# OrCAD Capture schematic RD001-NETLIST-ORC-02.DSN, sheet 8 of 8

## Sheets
8 1: size A3
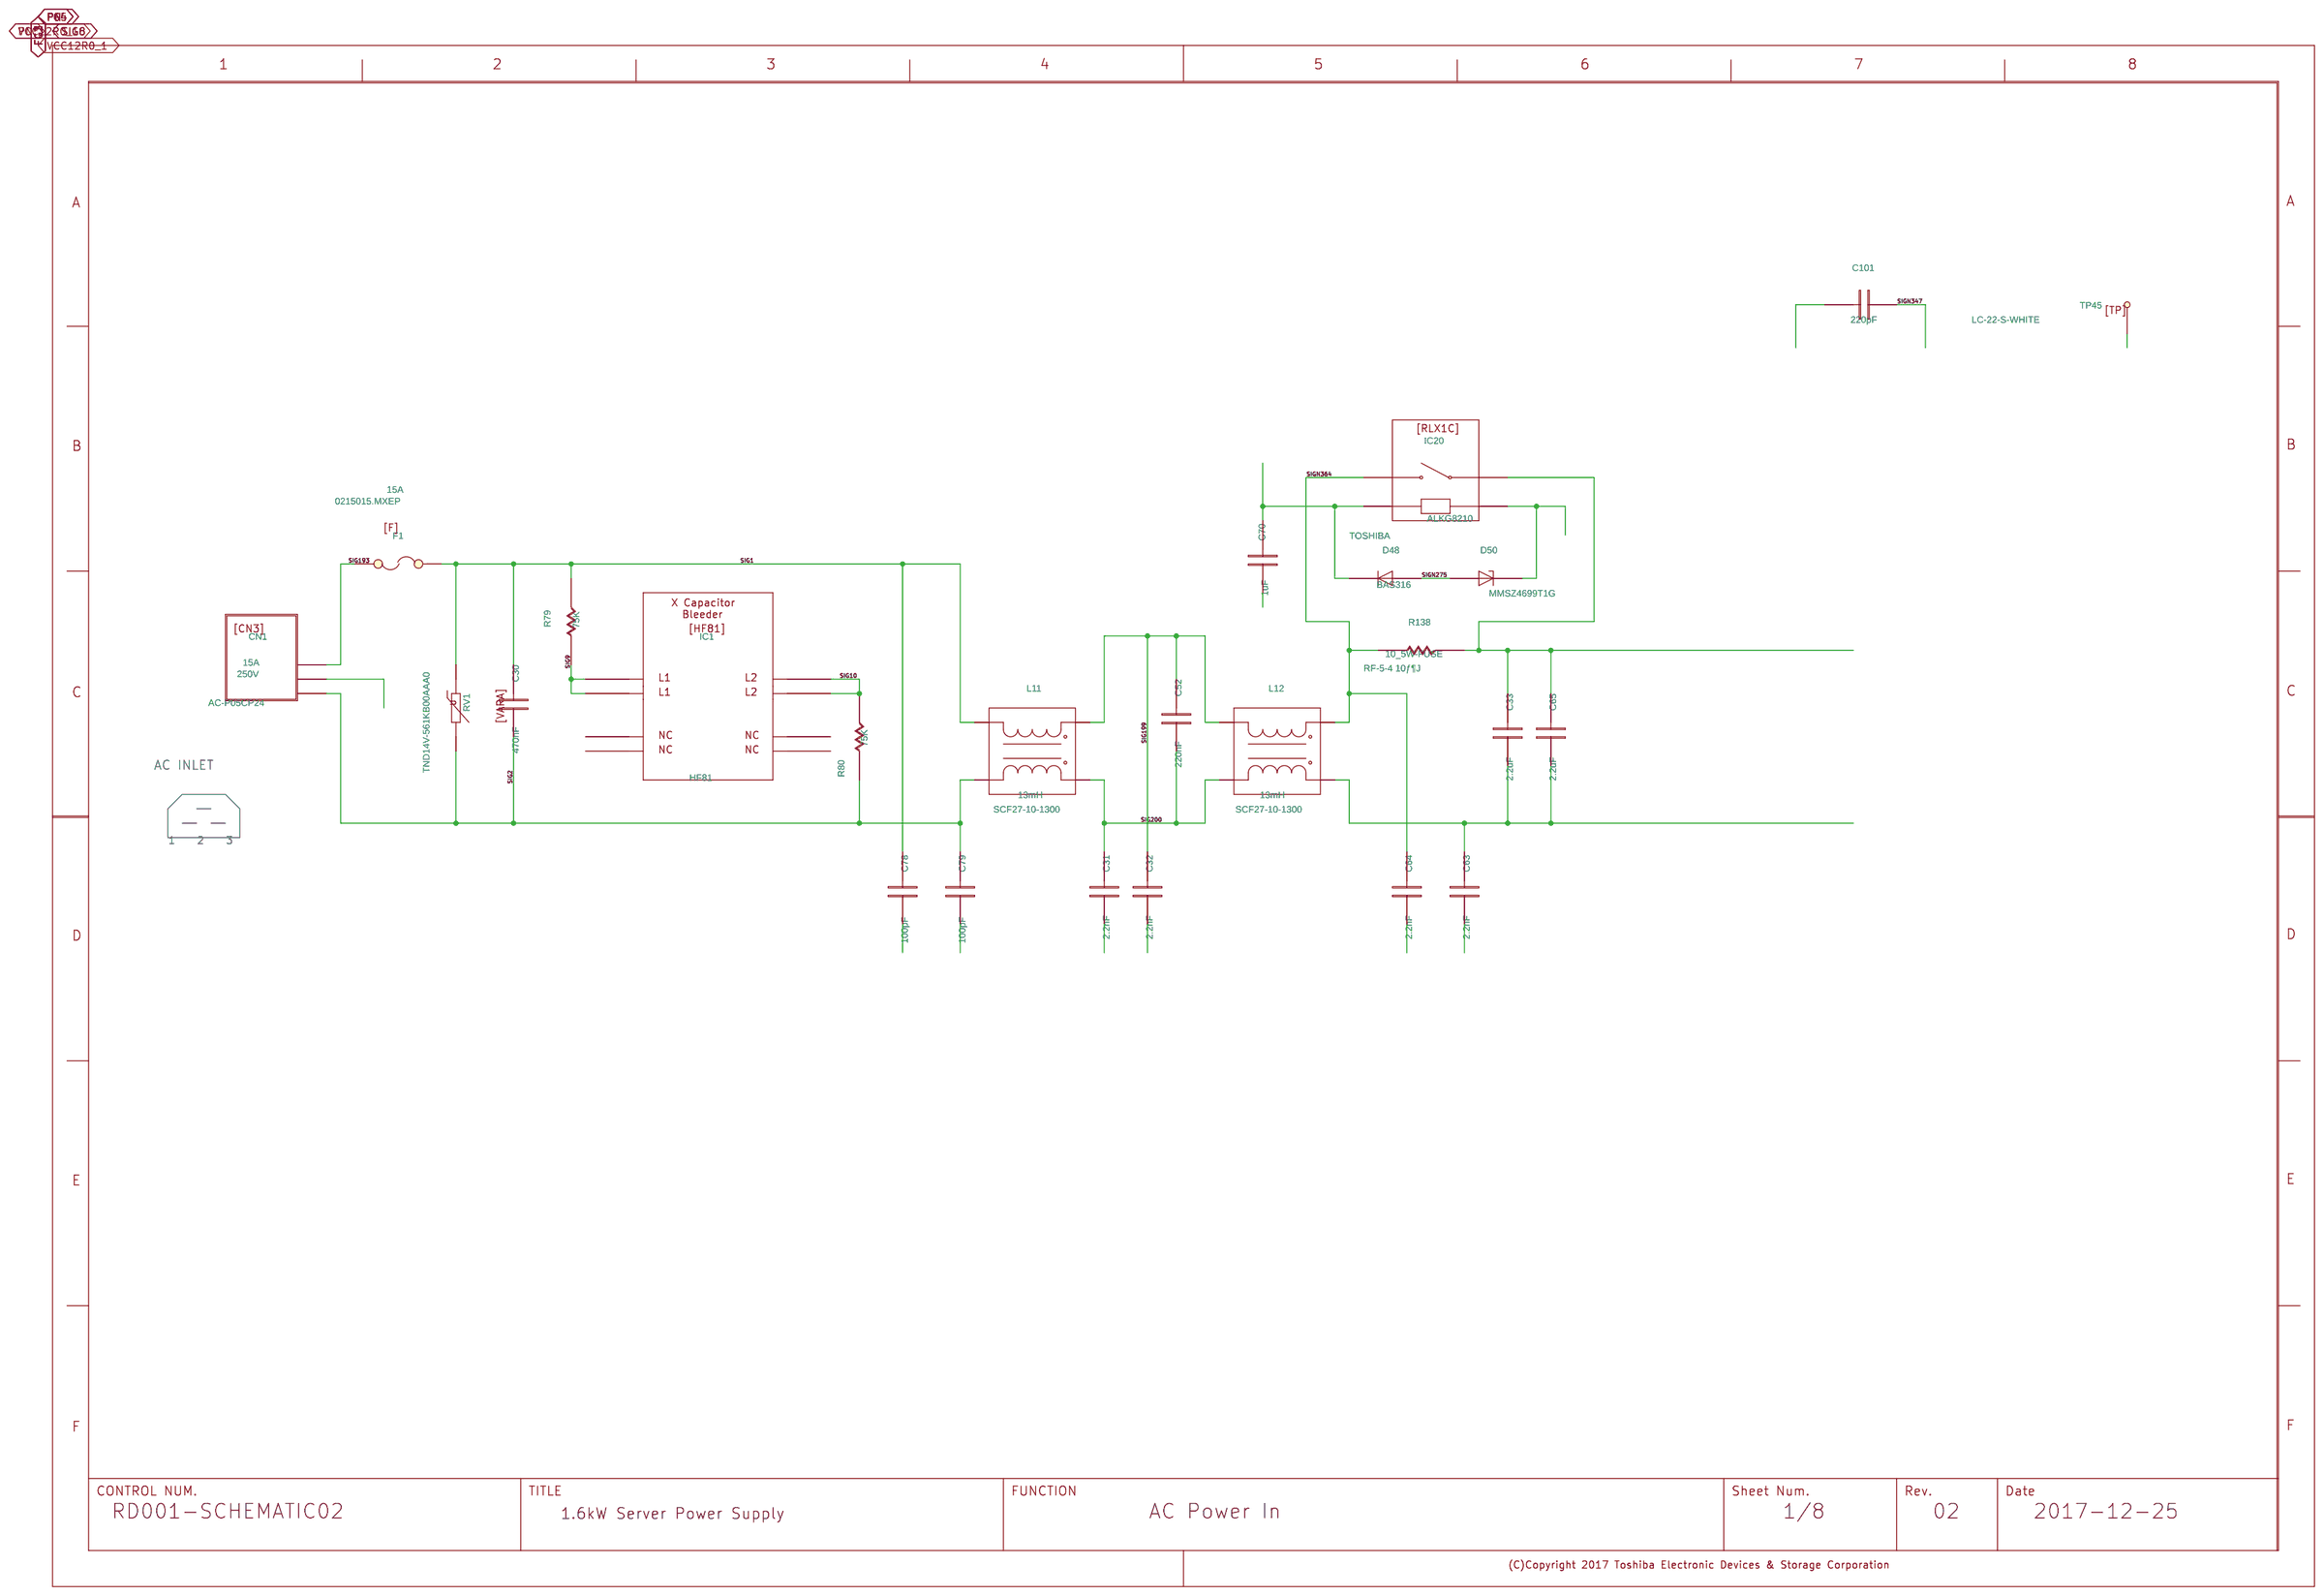
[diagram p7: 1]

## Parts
C30  C
C31  C
C32  C
C33  C
C52  C
C63  C
C64  C
C65  C
C70  C
C78  C
C79  C
C101  C
CN1  CN3
D48  D
D50  ZD
F1  F
IC1  L81
IC20  RLX1C
L11  HM-DLWHN6702
L12  HM-DLWHN6702
R79  R
R80  R
R138  R
RV1  VARA
TP45  TP
U?#7  WAKU_DEF100

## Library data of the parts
C30 = C: ADSMODELNAME: s_GRM32MR72A474KA01L; CAPACITANCETOLE: K; COMP: PRT_19; COMPONENTTYPE: 4; GCOUNT: 1; MAKER: OKAYA; MAXGCOUNT: 1; NOMINALCAPACITA: 470n; RATEDVOLTAGE: 100; SIZECODESMD: 3225; VAL1: 470nF; VAL2: 275V,}10%; VAL3: LE474-M
C31 = C: ADSMODELNAME: s_ECKNTS222ME; CAPACITANCETOLE: M; CDMASTERCADCELG: DC0284; CHIPSIZE: [hsb`7.5mmió]; COMP: PRT_13; COMPONENTTYPE: 4; FNLEADFREETHET1GT2GMCTH1: N_N_N; GCOUNT: 1; MAKER: MURATA; MAXGCOUNT: 1; NOMINALCAPACITA: 2.2n; OUMECLASSIFICATION: ƒZƒ‰ƒ~ƒbƒNƒRƒ“ƒfƒ“ƒT; OUMEMAKER: NAE pi\jbNGNgjbNfoCX; OUMEMAKERKATAMEI: ECKNTS222ME; PMPRODUCTSTYPEG: ES; QUADMODEL: CON_2.2N; RATEDVOLTAGE: 250; SIZECODESMD: DIP; TEMPCHARACTERI2: E; VAL1: 2.2nF; VAL2: 250V,}20%; VAL3: DE2E3KY222MN3AM02F
C32 = C: ADSCNVFLAG: ON; ADSMODELNAME: s_ECKNTS222ME; CAPACITANCETOLE: M; CDMASTERCADCELG: DC0284; CHIPSIZE: [hsb`7.5mmió]; COMP: PRT_13; COMPONENTTYPE: 4; FNLEADFREETHET1GT2GMCTH1: N_N_N; GCOUNT: 1; ICX_PART_MODEL: CON_2.2N; MAKER: MURATA; MAXGCOUNT: 1; NOMINALCAPACITA: 2.2n; OUMECLASSIFICATION: ƒZƒ‰ƒ~ƒbƒNƒRƒ“ƒfƒ“ƒT; OUMEMAKER: NAE pi\jbNGNgjbNfoCX; OUMEMAKERKATAMEI: ECKNTS222ME; PMPRODUCTSTYPEG: ES; QUADMODEL: CON_2.2N; RATEDVOLTAGE: 250; SIZECODESMD: DIP; SQ_PART_MODEL: CON_2.2N; TEMPCHARACTERI2: E; VAL1: 2.2nF; VAL2: 250V,}20%; VAL3: DE2E3KY222MN3AM02F
C33 = C: CAPACITANCETOLE: K; CDMASTERCADCELG: DC0511; COMP: PRT_18; COMPONENTTYPE: 4; FNLEADFREETHET1GT2GMCTH1: 9_N_N; GCOUNT: 1; MAKER: Wurth; MAXGCOUNT: 1; NOMINALCAPACITA: 2.2u; OUMECLASSIFICATION: ƒtƒBƒ‹ƒƒRƒ“ƒfƒ“ƒT; OUMEMAKER: CHM “ú–{ƒPƒ~ƒRƒ“; OUMEMAKERKATAMEI: TACB2E225K; QUADMODEL: CON_2.2U; RATEDVOLTAGE: 250; SIZECODESMD: DIP; VAL1: 2.2uF; VAL2: 275V,}10%; VAL3: 890324026034CS
C52 = C: CAPACITANCETOLE: M; COMP: PRT_17; COMPONENTTYPE: 4; FNLEADFREETHET1GT2GMCTH1: N_N_N; GCOUNT: 1; MAKER: OKAYA; MAXGCOUNT: 1; NOMINALCAPACITA: 220n; OUMECLASSIFICATION: ƒtƒBƒ‹ƒƒRƒ“ƒfƒ“ƒT; OUMEMAKER: NIS ƒjƒbƒZƒC“d‹@; OUMEMAKERKATAMEI: R40KI322000**M; QUADMODEL: CON_220N; RATEDVOLTAGE: 275; SIZECODESMD: DIP; VAL1: 220nF; VAL2: 275V,}10%; VAL3: LE224-M
C63 C64 = C: ADSMODELNAME: s_DE2E3KY222MN3AM02F; CAPACITANCETOLE: M; CDMASTERCADCELG: SIK0018; CHIPSIZE: [hsb`7.5mmió]; COMP: PRT_13; COMPONENTTYPE: 4; FNLEADFREETHET1GT2GMCTH1: N_N_N; GCOUNT: 1; MAKER: MURATA; MAXGCOUNT: 1; NOMINALCAPACITA: 2.2n; OUMECLASSIFICATION: ƒZƒ‰ƒ~ƒbƒNƒRƒ“ƒfƒ“ƒT; OUMEMAKER: MRT ºc»ì; OUMEMAKERKATAMEI: DE2E3KY222MN3AM02F; PMPRODUCTSTYPEG: PC1; QUADMODEL: CON_2.2N; RATEDVOLTAGE: 250; SIZECODESMD: DIP; TEMPCHARACTERI2: E; VAL1: 2.2nF; VAL2: 250V,}20%; VAL3: DE2E3KY222MN3AM02F
C65 = C: CAPACITANCETOLE: K; CDMASTERCADCELG: DC0511; COMP: PRT_18; COMPONENTTYPE: 4; FNLEADFREETHET1GT2GMCTH1: 9_N_N; GCOUNT: 1; MAKER: Wurth; MAXGCOUNT: 1; NOMINALCAPACITA: 2.2u; OUMECLASSIFICATION: ƒtƒBƒ‹ƒƒRƒ“ƒfƒ“ƒT; OUMEMAKER: CHM “ú–{ƒPƒ~ƒRƒ“; OUMEMAKERKATAMEI: TACB2E225K; QUADMODEL: CON_2.2U; RATEDVOLTAGE: 250; SIZECODESMD: DIP; VAL1: 2.2uF; VAL2: 270V,}10%; VAL3: 890324026034CS
C70 = C: ADSMODELNAME: s_GRM155B31E105KA12D; CAPACITANCETOLE: K; CDMASTERCADCELG: KC0005; CHIPSIZE: 1005; COMP: PRT_52; COMPONENTTYPE: 4; FNLEADFREETHET1GT2GMCTH1: 3_0_N; GCOUNT: 1; MAKER: TDK; MAXGCOUNT: 1; NOMINALCAPACITA: 1u; OUMECLASSIFICATION: ƒZƒ‰ƒ~ƒbƒNƒRƒ“ƒfƒ“ƒT; OUMEMAKER: MRT ºc»ì; OUMEMAKERKATAMEI: GRM155B31E105KA12D; PMPRODUCTSTYPEG: HD1; QUADMODEL: CON_1U; RATEDVOLTAGE: 25; SIZECODESMD: 1005; TEMPCHARACTERI2: B; VAL1: 1uF; VAL2: 25V,}20%; VAL3: C1005X5R1E105M050BC
C78 C79 = C: ADSMODELNAME: s_DE1B3KX101KA4BL01; CAPACITANCETOLE: K; CDMASTERCADCELG: RDK0051; CHIPSIZE: [hsb`7.5mmió]; COMP: PRT_29; COMPONENTTYPE: 4; FNLEADFREETHET1GT2GMCTH1: N_N_N; GCOUNT: 1; MAKER: MURATA; MAXGCOUNT: 1; NOMINALCAPACITA: 100p; OUMECLASSIFICATION: ƒZƒ‰ƒ~ƒbƒNƒRƒ“ƒfƒ“ƒT; OUMEMAKER: MRT ºc»ì; OUMEMAKERKATAMEI: DE1B3KX101KA4BL01; QUADMODEL: CON_100P; RATEDVOLTAGE: 250; TEMPCHARACTERI2: B; VAL1: 100pF; VAL2: 250V,}10%; VAL3: DE2B3KY101KA3BM02F
C101 = C: ADSMODELNAME: s_DEBB33A221KC1B; CAPACITANCETOLE: K; CDMASTERCADCELG: RD0002; COMP: PRT_50; COMPONENTTYPE: 4; FNLEADFREETHET1GT2GMCTH1: 9_1_N; GCOUNT: 1; MAKER: MURATA; MAXGCOUNT: 1; NOMINALCAPACITA: 220p; OUMECLASSIFICATION: ƒZƒ‰ƒ~ƒbƒNƒRƒ“ƒfƒ“ƒT; OUMEMAKER: MRT ºc»ì; OUMEMAKERKATAMEI: DEBB33A221KC1B; QUADMODEL: CON_220P; RATEDVOLTAGE: 1K; SIZECODESMD: DIP; TEMPCHARACTERI2: B; VAL1: 220pF; VAL2: 250V,}10%; VAL3: DE2B3KY221KA3BM02F
CN1 = CN3: COMP: PRT_61; COMPONENTTYPE: 4; MAKER: ECHO ELECTRIC; VAL1: 15A; VAL2: 250V; VAL3: AC-P05CP24
D48 = D: ADSMODELNAME: s_BAS16_02W; CDMASTERCADCELG: D8101D; COMP: PRT_26; COMPONENTTYPE: 4; FNLEADFREETHET1GT2GMCTH1: N_N_N; FORWARDVOLTAGEM: 0; GCOUNT: 1; MAKER: TOSHIBA; MAXAVERAGEFORWA: 0; MAXGCOUNT: 1; MAXREPETITIVEPE: 0; MAXREVERSEVOLTA: 0; MOUNTINGFORMSMD: SMD; OUMECLASSIFICATION: »Ì¼_CI[h; OUMEMAKER: IFO CtBjIeNmW[Y; OUMEMAKERKATAMEI: BAS16-02W; PEAKFORWARDVOLT: 0; REVERSECURRENT: 0; USERCOMPTEXT3: TOSHIBA; VAL3: BAS316; ZENERVOLTAGEMAX: 0; ZENERVOLTAGEMIN: 0
D50 = ZD: ADSMODELNAME: s_MMSZ4681T1G; CDMASTERCADCELG: MMK0127; COMP: PRT_47; COMPONENTTYPE: 4; FNLEADFREETHET1GT2GMCTH1: N_N_N; FORWARDVOLTAGEM: 0; GCOUNT: 1; MAKER: ON Semiconductor; MAXAVERAGEFORWA: 0; MAXGCOUNT: 1; MAXREPETITIVEPE: 0; MAXREVERSEVOLTA: 0; MOUNTINGFORMSMD: SMD; OUMECLASSIFICATION: èd³_CI[h; OUMEMAKER: ONS IZ~R_N^[; OUMEMAKERKATAMEI: MMSZ4681T1G; OUMEPARTTYPE: D; PEAKFORWARDVOLT: 0; REVERSECURRENT: 0; VAL3: MMSZ4699T1G; ZENERVOLTAGEMAX: 2.52; ZENERVOLTAGEMIN: 2.28
F1 = F: COMP: PRT_21; COMPONENTTYPE: 4; GCOUNT: 1; MAKER: Littelfuse; MAXGCOUNT: 1; MOUNTINGFORMSMD: SMD; NOMINALOPERATIO: 0; RATEDINTERRUPTI: 0; RATEDVOLTAGE: 0; VAL1: 15A; VAL3: 0215015.MXEP
IC1 = L81: COMP: PRT_45; COMPONENTTYPE: 4; MAKER: MPS; VAL3: HF81
IC20 = RLX1C: AUTHOR: ikeda-k; COMP: PRT_1; COMPONENTKIND: 115; COMPONENTTYPE: 4; DATE: 2003/02/07; MAKER: PANASONIC; SAVEAREA0: -15461,-296,40419,28727; TIME: 14:49:55; UPDATEDATE: 2017/01/13; UPDATETIME: 11:13:08; UPDATEUSER: cae; VAL3: ALKG8210
L11 L12 = HM-DLWHN6702: COMP: PRT_22; COMPONENTTYPE: 4; MAKER: NEC TOKIN; VAL1: 13mH; VAL3: SCF27-10-1300
R79 R80 = R: ADSMODELNAME: s_RK73H2ETE563F; CDMASTERCADCELG: DR903A; CHIPSIZE: 3225; COMP: PRT_23; COMPONENTTYPE: 4; FNLEADFREETHET1GT2GMCTH1: N_N_N; GCOUNT: 1; MAKER: PANASONIC; MAXGCOUNT: 1; MOUNTINGFORMSMD: SMD; NOMINALRESISTAN: 56K; OUMECLASSIFICATION: \ÊÀpÅèïRí; OUMEMAKER: KOA R[A; OUMEMAKERKATAMEI: RK73H2ETE563F; POWERRATING: 250m; QUADMODEL: RES_56K; RESISTANCETOLER: F; SIZECODESMD: 3225; VAL1: 75K; VAL2: 500mW,}1%; VAL3: ERJ-14NF7502U
R138 = R: CHIPSIZE: 13x9xH25.5; COMP: PRT_33; COMPONENTTYPE: 4; MAKER: TAKMAN; VAL1: 10_5W-FUSE; VAL3: RF-5-4 10ƒ¶J
RV1 = VARA: CDMASTERCADCELG: KC0008; COMP: PRT_37; COMPONENTTYPE: 4; FNLEADFREETHET1GT2GMCTH1: N_N_N; GCOUNT: 1; MAKER: NIPPON CHEMICON; MAXGCOUNT: 1; MOUNTINGFORMSMD: SMD; OUMECLASSIFICATION: ƒoƒŠƒXƒ^; OUMEMAKER: TDK ‚s‚c‚j; OUMEMAKERKATAMEI: AVR-M1608C220KT6AB; OUMEPARTTYPE: RV; RATEDVOLTAGE: 0; VAL1: 560V; VAL3: TND14V-561KB00AAA0
TP45 = TP: COMP: PRT_49; COMPONENTKIND: 111; COMPONENTTYPE: 4; MAKER: MAC8; VAL3: LC-22-S-WHITE
U?#7 = WAKU_DEF100: COMPONENTTYPE: 2; DATE: 2017-12-25; DESIGNED: TOSHIBA; DRAWINGNUMBER: RD001-SCHEMATIC02; FUNCTION: AC Power In; PAGENUMBER: 2; REVISION: 02; SAVEAREA0: -45080,-4508,463680,304612; SHEETNUMBER: 1/8; TIME: 10:19:22; TITLE: 1.6kW Server Power Supply; UPDATEDATE: 2017/12/25; UPDATETIME: 13:49:58; UPDATEUSER: f1043010

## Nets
VCC12R0_1: C70.2 D48.C IC20.1 ; also on sheet 5 6 7
FG1: CN1.2
FG2: C79.1
FG3: C32.1 C64.1 C78.1
FG4: C31.1 C63.1
FG5: C101.2
PN: C70.1 C101.1 D50.C IC20.2 TP45.1 ; also on sheet 2 5 6 7
SIG1: C30.2 C78.2 F1.2 L11.2 R79.2 RV1.1
SIG2: C30.1 C79.2 CN1.3 L11.3 R80.1 RV1.2
SIG6: C33.1 C63.2 C65.1 L12.4 ; also on sheet 7
SIG8: C33.2 C65.2 IC20.3 R138.2 ; also on sheet 7
SIG9: IC1.2 IC1.3 R79.1
SIG10: IC1.6 IC1.7 R80.2
SIG193: CN1.1 F1.1
SIG199: C32.2 C52.2 L11.1 L12.2
SIG200: C31.2 C52.1 L11.4 L12.3
SIGN275: D48.A D50.A
SIGN364: C64.2 IC20.4 L12.1 R138.1

Not connected (* = marked no-connect by the designer): IC1 1 4 5 8

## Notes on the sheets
sheet 8
- AC INLET
- 1
- 2
- 3
